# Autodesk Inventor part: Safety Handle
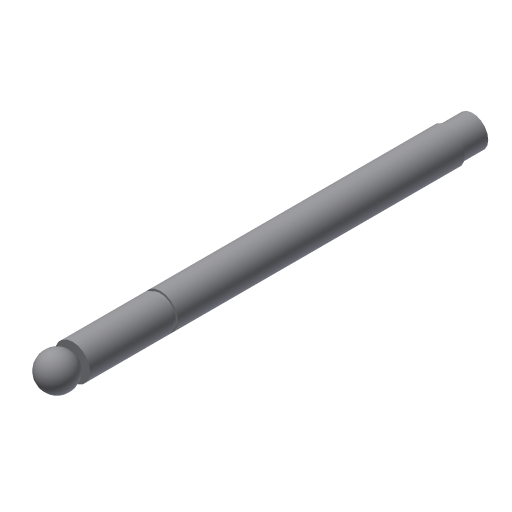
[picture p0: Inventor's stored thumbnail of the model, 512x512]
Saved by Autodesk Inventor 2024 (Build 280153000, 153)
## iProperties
Shininess: 77.0
Length Units: 11269
Angle Units: 11279
Time Units: 11290
Mass Units: 11283
Length Display Precision: 3
Angle Display Precision: 2
Created: 2002-02
Part Number: Safety Handle
Document SubType Name: Modeling
Designer: ***
Density: 1 g/cm^3
Material: Generic
Appearance: Default
Density: 0.0
Volumn: 0.0
Area: 0.0
PropertySet Name: Model Information
Control State: 0
Master: False
Checked Out: False
Author: ***
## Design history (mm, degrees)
sketch "Sketch1"
  geometry: L1 (0, 205)-(8, 205); L2 (8, 205)-(8, 192); L3 (8, 192)-(9, 192); L4 (9, 192)-(9, 45); L5 (9, 45)-(8, 45); L6 (8, 45)-(8, 43); L7 (8, 43)-(9, 43); L8 (9, 43)-(9, 0); L9 (9, 0)-(0, 0); L10 (0, 0)-(0, 205)
  constraints: 20 end point, 7 parallel, 1 collinear, 1 horizontal, 1 perpendicular
  dimensions: "d0" = 13 distance of L1.end L2.end; "d1" = 2 distance of L4.end L7.end; "d2" = 43 distance of L7.end L8.end; "d3" = 205 distance of L9.end L1.start; "d4" = 16 diameter of L2 L10; "d5" = 18 diameter of L4 L10; "d6" = 16 diameter of L6.end L10
revolve "Revolution1" sketch "Sketch1" stored, may be unused: angle "d7" = 90 deg
sketch "Sketch2"
  geometry: L1 (0, 1)-(0, -17); L2 (-9, 0)-(9, 0) reference; A1 r 9 centre (0, -8) between (0, -17) and (0, 1)
  constraints: 2 end point, 2 point on circle, 1 centre point, 1 midpoint, 1 vertical
  dimensions: "d8" = 9 radius of A1; "d9" = 1 distance from line of L2 L1.start
revolve "Revolution2" sketch "Sketch2" stored, may be unused: angle "d10" = 90 deg
body "Solid1"
